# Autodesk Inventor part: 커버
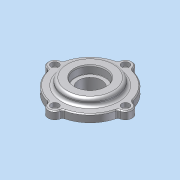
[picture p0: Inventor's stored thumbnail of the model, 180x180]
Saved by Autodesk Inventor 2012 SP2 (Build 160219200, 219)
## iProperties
Company: 한국ATC센터
Created: 2015-03
Part Number: 커버
Document SubType Name: Modeling
Designer: KYOUNG IL JANG
Density: 1 g/cm^3
Material: 기본값
Author: KYOUNG IL JANG
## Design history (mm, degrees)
sketch "스케치1"
  geometry: C1 r 1.621 at (0, 6.75) reference; C2 r 1.621 at (-37, -30.25) reference; C3 r 1.621 at (0, -67.25) reference; C4 r 1.621 at (37, -30.25) reference; C5 r 10 at (0, -30.25) reference; C6 r 12 at (0, -30.25); C7 r 24.5 at (0, -30.25) reference; A1 r 3 centre (-38.77, -20.408) between (-38.239, -23.361) and (-35.862, -21.146) reference; A2 r 7 centre (-37, -30.25) between (-38.239, -23.361) and (-38.239, -37.139) reference; A3 r 3 centre (-38.77, -40.092) between (-35.862, -39.354) and (-38.239, -37.139) reference; A4 r 37 centre (0, -30.25) between (-35.862, -39.354) and (-9.104, -66.113) reference; A5 r 3 centre (-9.842, -69.02) between (-6.889, -68.489) and (-9.104, -66.113) reference; A6 r 7 centre (0, -67.25) between (-6.889, -68.489) and (6.889, -68.489) reference; A7 r 3 centre (9.842, -69.02) between (9.104, -66.112) and (6.889, -68.489) reference; A8 r 37 centre (0, -30.25) between (9.104, -66.112) and (35.863, -39.354) reference; A9 r 3 centre (38.77, -40.092) between (38.239, -37.139) and (35.863, -39.354) reference; A10 r 7 centre (37, -30.25) between (38.239, -37.139) and (38.239, -23.361) reference; A11 r 3 centre (38.77, -20.408) between (35.863, -21.146) and (38.239, -23.361) reference; A12 r 37 centre (0, -30.25) between (35.863, -21.146) and (9.104, 5.612) reference; A13 r 3 centre (9.842, 8.52) between (6.889, 7.989) and (9.104, 5.612) reference; A14 r 7 centre (0, 6.75) between (6.889, 7.989) and (-6.889, 7.989) reference; A15 r 3 centre (-9.842, 8.52) between (-9.104, 5.612) and (-6.889, 7.989) reference; A16 r 37 centre (0, -30.25) between (-9.104, 5.612) and (-35.862, -21.146) reference; 1 further point
  constraints: 1 centre point, 1 coincident
  dimensions: "d2" = 2 radial gap between concentric circles of C6 C5
extrude "돌출1" new body sketch "스케치1" distance "d0" = 8; taper "d1" = 0 deg
sketch "스케치2"
  geometry: C1 r 23.5 at (0, -30.25) reference; C2 r 12 at (0, -30.25) reference; 1 further point
extrude "돌출2" join sketch "스케치2" distance "d4" = 5; taper "d5" = 0 deg
sketch "스케치3"
  geometry: C1 r 23.5 at (0, 0) reference; C2 r 20.5 at (0, 0); 1 further point
  constraints: 1 centre point
  dimensions: "d6" = 3 radial gap between concentric circles of C2 C1
node "작업 평면1"
extrude "돌출3" join sketch "스케치3" stored distance "d7" = 5; taper "d8" = 0 deg
fillet "모깎기1" dims "d9" = 3
sketch "스케치4"
  geometry: C1 r 12 at (0, -30.25) reference; C2 r 27 at (0, -30.25); 1 further point
  constraints: 1 centre point
  dimensions: "d10" = 15 radial gap between concentric circles of C1 C2
extrude "돌출4" join sketch "스케치4" distance "d11" = 7; taper "d12" = 0 deg
fillet "모깎기2" dims "d13" = 3
chamfer "모따기1" distance "d14" = 1; stored, may be unused: second distance "d15" = 2, angle "d16" = 45 deg
node "작업점1"
  node "작업축1"
chamfer "모따기2" distance "d24" = 1; stored, may be unused: second distance "d25" = 2, angle "d26" = 45 deg
hole "구멍6" diameter "d43" = 4.5; stored, may be unused: countersink angle "d47" = 90 deg, drill point angle "d49" = 118 deg; dims "d41" = 10, "d42" = 10, "d44" = 6, "d45" = 8, "d46" = 4.4, "d48" = 8
sketch "스케치8"
  geometry: C1 r 12 at (0, 0) reference; C2 r 16 at (0, 0); 1 further point
  constraints: 1 centre point, 1 coincident
  dimensions: "d53" = 32 diameter of C2
extrude "돌출5" cut sketch "스케치8" distance "d54" = 8.3; taper "d55" = 0 deg
fillet "모깎기3" dims "d56" = 0.3
chamfer "모따기3" distance "d57" = 1.2; stored, may be unused: second distance "d58" = 2, angle "d59" = 30 deg
node "솔리드1"
pattern_circular "원형 패턴1" dims angle "d51" = 360 deg
node "참조1"
node "참조2"
